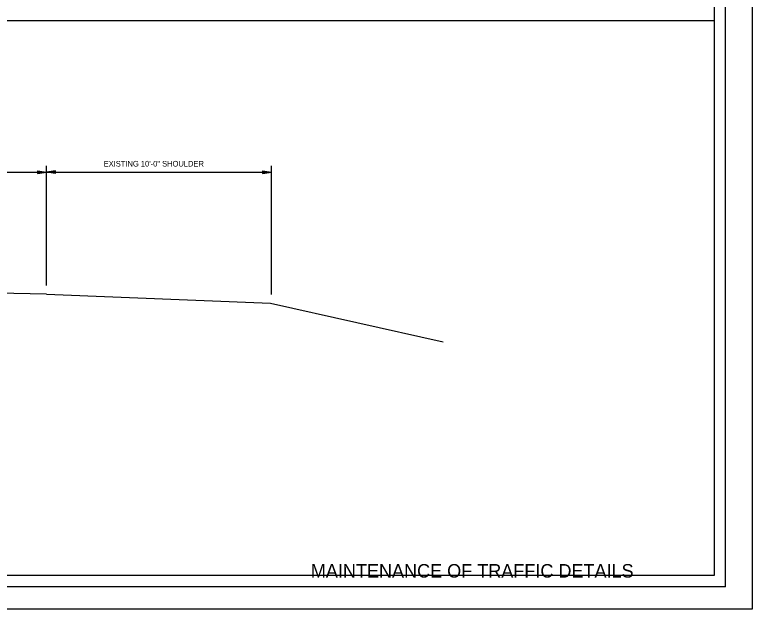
# Model space of a CAD drawing. Extents: x -500 to 213, y 382723 to 382830.
# Drawn here: x 147.8 to 213.4, y 382723.1 to 382776 of the extents above; entities that cross this region are included whole.
import ezdxf

# ---------------------------------------------------------------- set-up
doc = ezdxf.new("R2010")
doc.units = 0
for name, color, linetype in [('Default', 7, 'Continuous'), ('R_Border', 7, 'Continuous'), ('R_Border Title', 7, 'Continuous'), ('R_No Plot', 7, 'Continuous')]:
    doc.layers.add(name, color=color, linetype=linetype)

msp = doc.modelspace()

# ---------------------------------------------------------------- linework, layer by layer
at = {"layer": 'Default'}
for p, q in [((150.664, 382761.029), (150.664, 382762.54)), ((170.668, 382761.181), (170.668, 382762.54)), ((126.66, 382761.99), (150.664, 382761.99)), ((149.864, 382762.11), (150.664, 382761.99)), ((149.864, 382762.11), (149.864, 382761.869)), ((149.864, 382762.09), (150.53, 382761.99)), ((149.864, 382762.07), (150.392, 382761.99)), ((149.864, 382762.05), (150.26, 382761.99)), ((149.864, 382762.03), (150.124, 382761.99)), ((149.864, 382762.01), (149.99, 382761.99)), ((149.864, 382761.869), (150.664, 382761.99)), ((149.864, 382761.952), (150.124, 382761.99)), ((149.864, 382761.909), (150.392, 382761.99)), ((149.864, 382761.889), (150.53, 382761.99)), ((149.864, 382761.929), (150.26, 382761.99)), ((149.864, 382761.972), (149.99, 382761.99)), ((151.465, 382762.11), (150.664, 382761.99)), ((150.664, 382761.99), (170.668, 382761.99)), ((151.465, 382761.869), (150.664, 382761.99)), ((151.465, 382762.09), (150.798, 382761.99)), ((151.465, 382761.889), (150.798, 382761.99)), ((151.465, 382762.07), (150.936, 382761.99)), ((151.465, 382761.909), (150.936, 382761.99)), ((151.465, 382762.05), (151.069, 382761.99)), ((151.465, 382761.929), (151.069, 382761.99)), ((151.465, 382762.03), (151.205, 382761.99)), ((151.465, 382761.952), (151.205, 382761.99)), ((151.465, 382762.01), (151.339, 382761.99)), ((151.465, 382761.972), (151.339, 382761.99)), ((151.465, 382761.869), (151.465, 382762.11)), ((169.868, 382762.11), (170.668, 382761.99)), ((169.868, 382762.11), (169.868, 382761.869)), ((169.868, 382762.09), (170.534, 382761.99)), ((169.868, 382762.07), (170.396, 382761.99)), ((169.868, 382762.05), (170.264, 382761.99)), ((169.868, 382762.03), (170.128, 382761.99)), ((169.868, 382762.01), (169.994, 382761.99)), ((169.868, 382761.869), (170.668, 382761.99)), ((169.868, 382761.952), (170.128, 382761.99)), ((169.868, 382761.909), (170.396, 382761.99)), ((169.868, 382761.889), (170.534, 382761.99)), ((169.868, 382761.929), (170.264, 382761.99)), ((169.868, 382761.972), (169.994, 382761.99)), ((150.664, 382751.904), (150.664, 382761.029)), ((170.668, 382751.105), (170.668, 382761.181)), ((150.664, 382751.143), (126.66, 382751.623)), ((150.664, 382751.143), (170.592, 382750.347)), ((170.592, 382750.347), (185.951, 382746.907))]:
    msp.add_line(p, q, dxfattribs=at)
at = {"layer": 'R_Border'}
for q in [(211.057, 382827.85), (52.967, 382725.12)]:
    msp.add_line((211.057, 382725.12), q, dxfattribs=at)
at = {"layer": 'R_No Plot'}
for points in [[(46.763, 382829.798), (213.433, 382829.798), (213.433, 382723.129), (46.763, 382723.129)], [(53.967, 382826.85), (178.737, 382826.85), (178.737, 382821.91), (187.507, 382821.91), (199.557, 382821.91), (199.557, 382810.744), (210.057, 382810.744), (210.057, 382726.12), (53.967, 382726.12)], [(53.967, 382775.485), (210.057, 382775.485), (210.057, 382726.12), (53.967, 382726.12)]]:
    msp.add_lwpolyline(points, close=True, dxfattribs=at)

# ---------------------------------------------------------------- texts
at = {"layer": 'Default'}
msp.add_text('EXISTING 10\'-0" SHOULDER', height=0.5001, dxfattribs=at).set_placement((155.754, 382762.491))
at = {"layer": 'R_Border Title'}
msp.add_text('MAINTENANCE OF TRAFFIC DETAILS', height=1.2, dxfattribs=at).set_placement((174.176, 382725.945))

doc.saveas('drawing.dxf')
